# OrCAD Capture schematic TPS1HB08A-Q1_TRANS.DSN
size E; title: TPS1HB08A-Q1 40-V, 8-mOhm Single-Channel Smart; rev: 1.0; note: Datasheet: SLVSE16C     EVM: SLVUBD4B; note: High-Side Switch
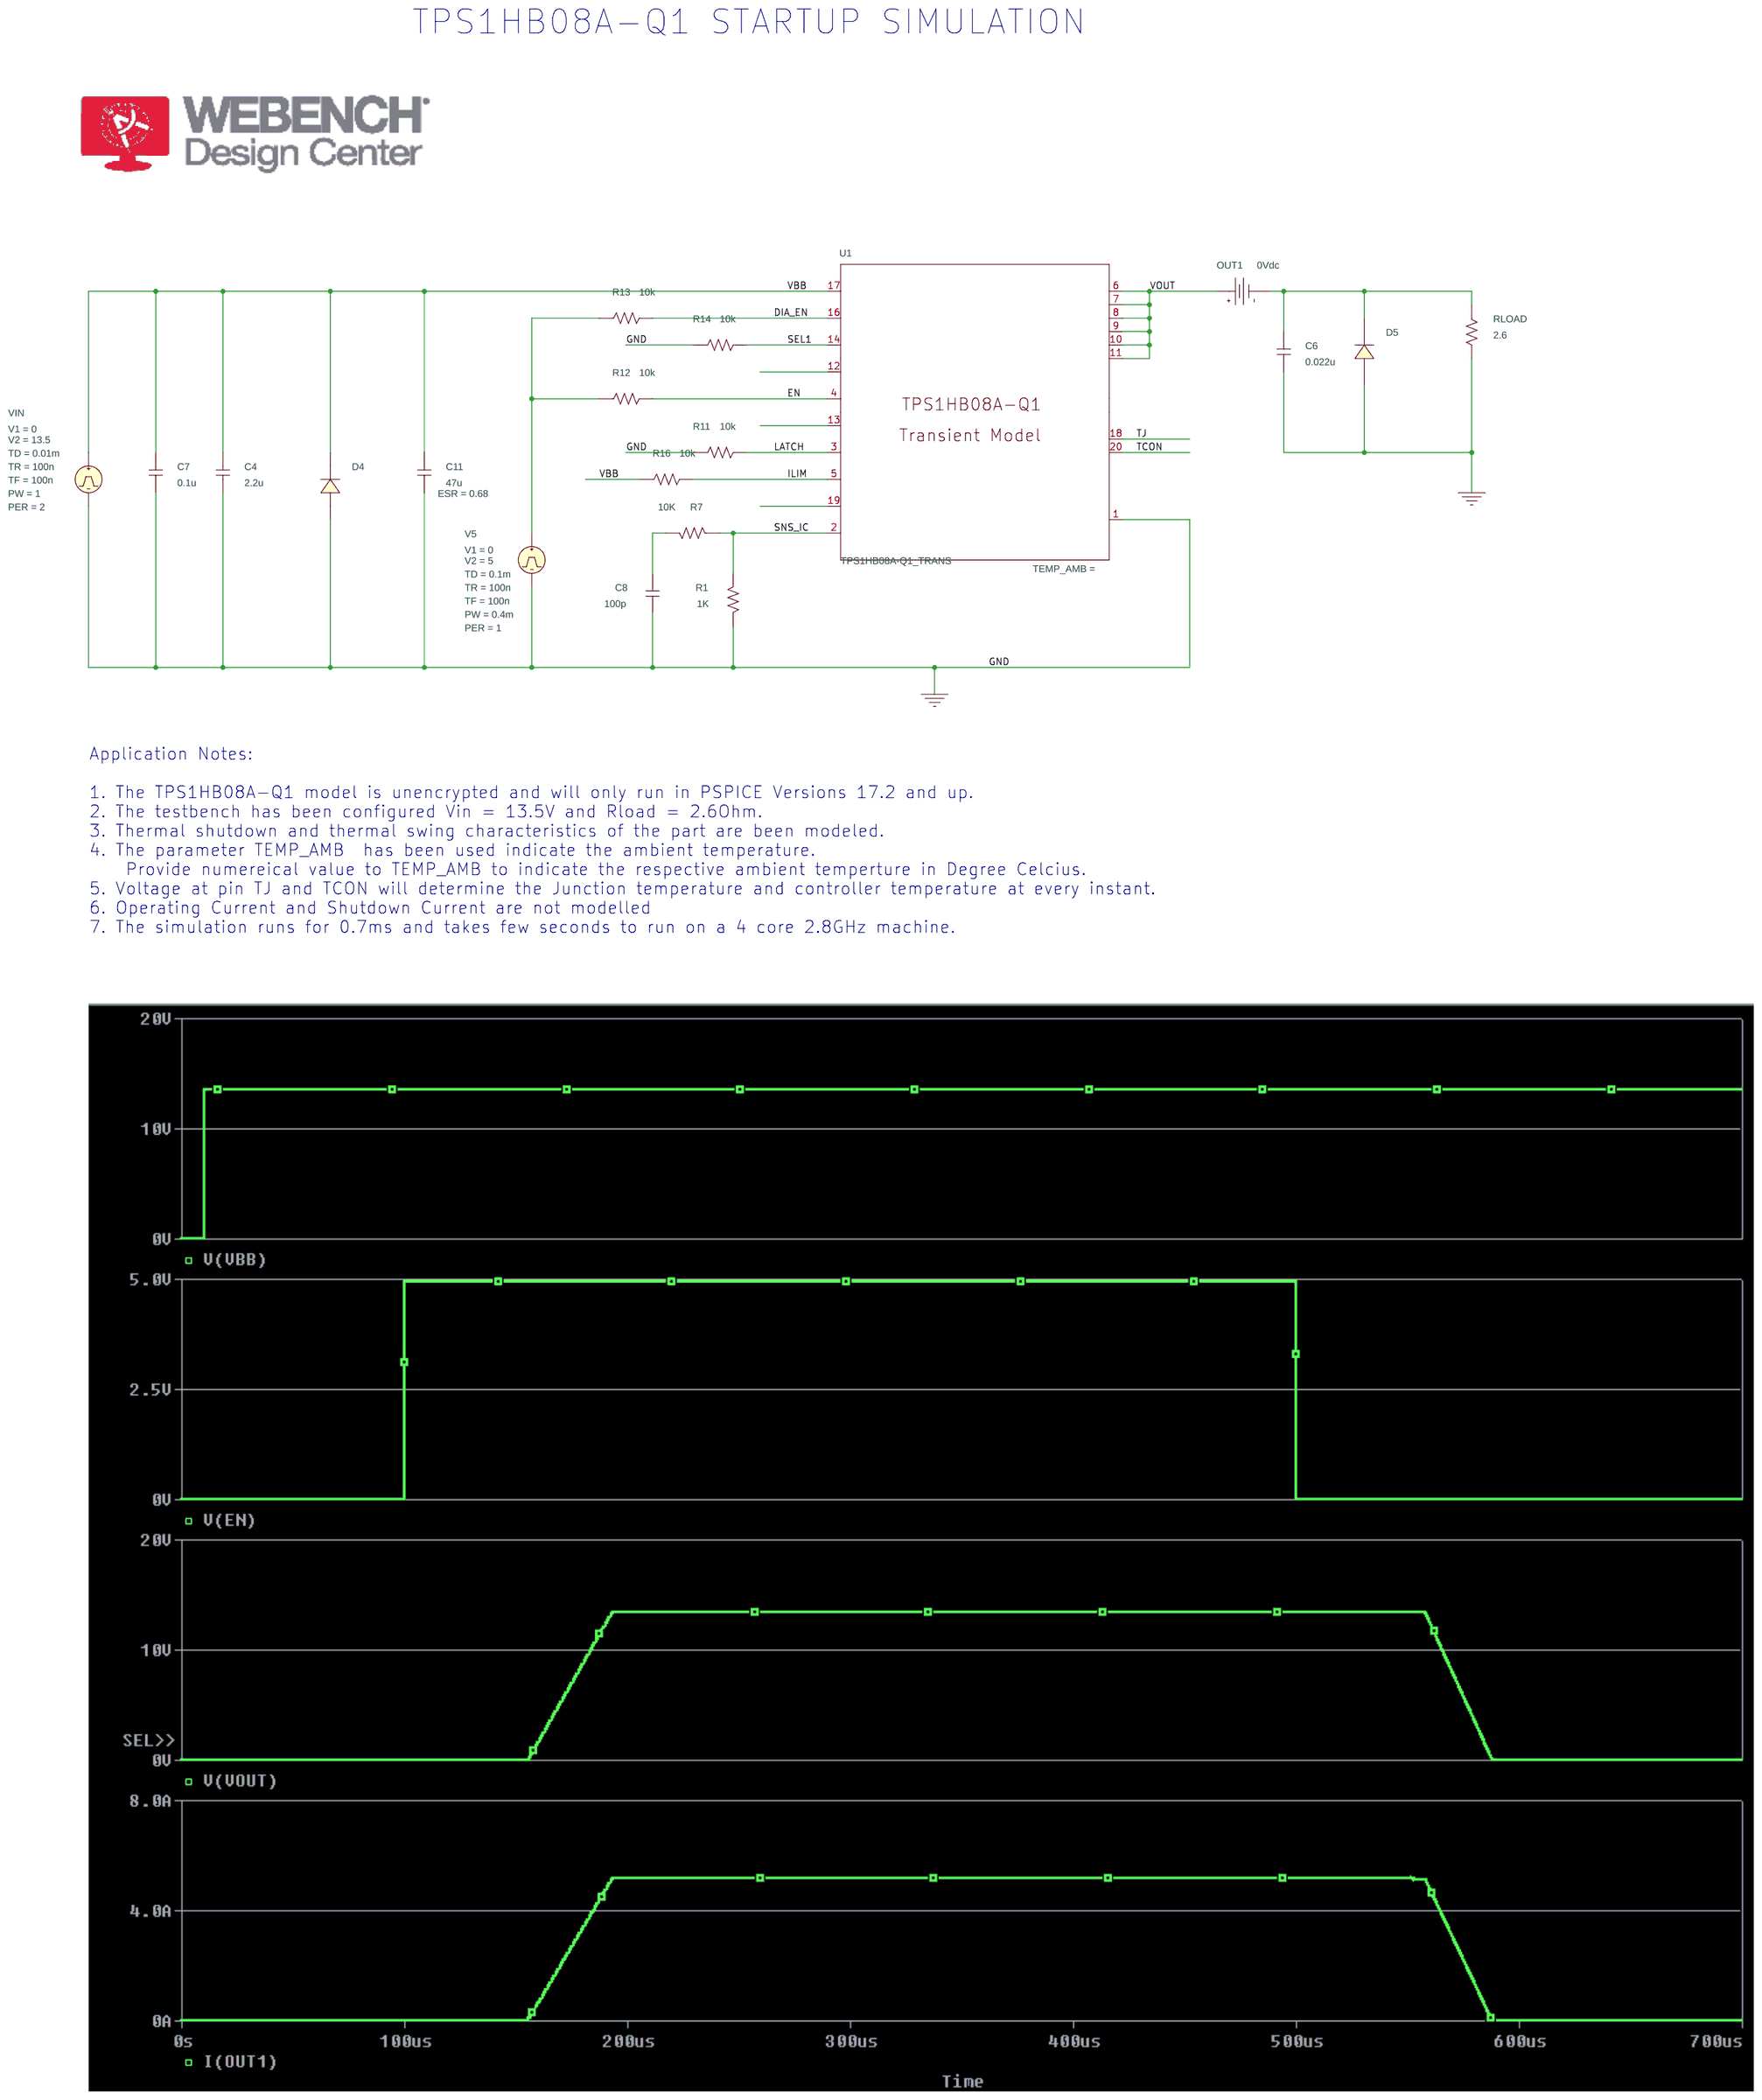
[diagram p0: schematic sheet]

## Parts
C4  2.2u  [RAD/CK05]
C6  0.022u  [RAD/CK05]
C7  0.1u  [RAD/CK05]
C8  100p  [RAD/CK05]
C11  47u  [RAD/CK05]
D4  SMCJ33A
D5  SMCJ33A
OUT1  VDC
R1  1K  [AX/RC05]
R7  10K  [AX/RC05]
R11  10k  [AX/RC05]
R12  10k  [AX/RC05]
R13  10k  [AX/RC05]
R14  10k  [AX/RC05]
R16  10k  [AX/RC05]
RLOAD  2.6  [AX/RC05]
U1  TPS1HB08A-Q1_TRANS  [PWP0016M_N]
V5  VPULSE
VIN  VPULSE

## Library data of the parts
C4 C6-C8 = C
C11 = C: AppProp: InductiveSlave:;SRF:;PrevCap:47u;PrevESL:; ESR: 0.68
D4 D5 = D_D1: PSpiceTemplate: D^@REFDES  %1 %2 @MODEL ?AREA/@AREA/
OUT1 = VDC: DC: 0Vdc
R1 R7 R11-R14 R16 RLOAD = R
U1 = TPS1HB08A-Q1_TRANS: PSpiceTemplate: X^@REFDES  %DIA_EN %EN %GND %ILIM %LATCH %NC_0 %NC_1 %NC_2 %SEL1 %SNS %TCON %TJ %VBB %VOUT_0 %VOUT_1 %VOUT_2 %VOUT_3 %VOUT_4 %VOUT_5 @MODEL PARAMS: ?TEMP_AMB|TEMP_AMB=@TEMP_AMB||TEMP_AMB=25|
V5 = VPULSE: PER: 1; PW: 0.4m; TD: 0.1m; TF: 100n; TR: 100n; V1: 0; V2: 5
VIN = VPULSE: PER: 2; PW: 1; TD: 0.01m; TF: 100n; TR: 100n; V1: 0; V2: 13.5

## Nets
0: C4.2 C6.2 C7.2 C8.2 C11.1 D4.1 D5.1 R1.1 R11.1 R14.1 RLOAD.2 U1.1(GND) V5.2(-) VIN.2(-)
DIA_EN: R13.2 U1.16(DIA_EN)
EN: R12.2 U1.4(EN)
ILIM: R16.2 U1.5(ILIM)
LATCH: R11.2 U1.3(LATCH)
SEL1: R14.2 U1.14(SEL1)
SNS_IC: R1.2 R7.1 U1.2(SNS)
TCON: U1.20(TCON)
TJ: U1.18(TJ)
VBB: C4.1 C7.1 C11.2 D4.2 R16.1 U1.17(VBB) VIN.1(+)
VOUT: OUT1.0(+) U1.6(VOUT_0) U1.7(VOUT_1) U1.8(VOUT_2) U1.9(VOUT_3) U1.10(VOUT_4) U1.11(VOUT_5)
N02414: C6.1 D5.2 OUT1.1(-) RLOAD.1
N06778: R12.1 R13.1 V5.1(+)
N08043: C8.1 R7.2

Not connected (* = marked no-connect by the designer): U1 12(NC_0) 13(NC_1) 19(NC_2)

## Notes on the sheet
- TPS1HB08A-Q1 STARTUP SIMULATION
- Application Notes:
  1. The TPS1HB08A-Q1 model is unencrypted and will only run in PSPICE Versions 17.2 and up.
  2. The testbench has been configured Vin = 13.5V and Rload = 2.6Ohm.
  3. Thermal shutdown and thermal swing characteristics of the part are been modeled.
  4. The parameter TEMP_AMB  has been used indicate the ambient temperature.
      Provide numereical value to TEMP_AMB to indicate the respective ambient temperture in Degree Celcius.
  5. Voltage at pin TJ and TCON will determine the Junction temperature and controller temperature at every instant.
  6. Operating Current and Shutdown Current are not modelled
  7. The simulation runs for 0.7ms and takes few seconds to run on a 4 core 2.8GHz machine.
